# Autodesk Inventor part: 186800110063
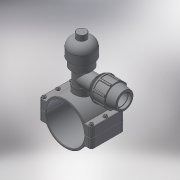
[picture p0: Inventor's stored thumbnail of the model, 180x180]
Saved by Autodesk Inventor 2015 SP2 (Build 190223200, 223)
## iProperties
Created: 2017-05
Part Number: 186800110063
Material: Generic
Description: PLASSON MECHANICAL TAPPING VALVE 110-63
Document SubType Name: Modeling
Designer: KIM
Density: 1 g/cm^3
Appearance: Default
Author: KIM
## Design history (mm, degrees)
derived "18680.ipt"
feature "Solid1::18680.ipt"
feature "Solid2::18680.ipt"
tag "TaggingFeature1"
body "Solid1"
other parameters: "d0" = 121, "d1" = 165, "d2" = 55, "d4" = 116, "d5" = 0, "d6" = 8.25, "d7" = 165, "d8" = 0.1, "d10" = 0, "d11" = 1.1, "d14" = 73.6528, "d20" = 1.1, "d23" = 1.1, "d36" = 13, "d37" = 10.4, "d38" = 63, "d39" = 0, "d40" = 3, "d41" = 5, "d42" = 0, "d43" = 8, "d44" = 3, "d45" = 0, "d46" = 1.1, "d51" = 87, "d52" = 56.656, "d53" = 21, "d54" = 0, "d57" = 0, "d58" = 118.8, "d60" = 0, "d62" = 13, "d63" = 10.4, "d66" = 95.2, "d67" = 63, "d68" = 16.66667, "d70" = 113, "d71" = 84.75, "d72" = 2.85714, "d73" = 90.4, "d74" = 120 deg, "d75" = 81.9, "d76" = 10 deg, "d77" = 101.7, "d80" = 50.4, "d82" = 11, "d87" = 28.57143, "d90" = 105.09, "d91" = 35 deg, "d92" = 17.5 deg, "d94" = 0, "d96" = 360 deg, "d98" = 1.26, "d99" = 121, "d100" = 67.8, "d101" = 135 deg, "d102" = 2.26, "d105" = 5.65, "d106" = 0, "d107" = 0.1, "d109" = 73.6528, "d112" = 34.85714, "d113" = 6.66667, "d116" = 0, "d121" = 67.9872, "d122" = 113.312, "d123" = 96.3152, "d124" = 45 deg, "d125" = 219.6, "d126" = 244, "d127" = 146.4, "d128" = 1, "d129" = 65, "G_" = 56.656, "A_" = 87, "L_" = 165, "L_1" = 116, "l_2" = 21, "d_1" = 63, "E_" = 113, "H_1" = 65, "H_2" = 244
